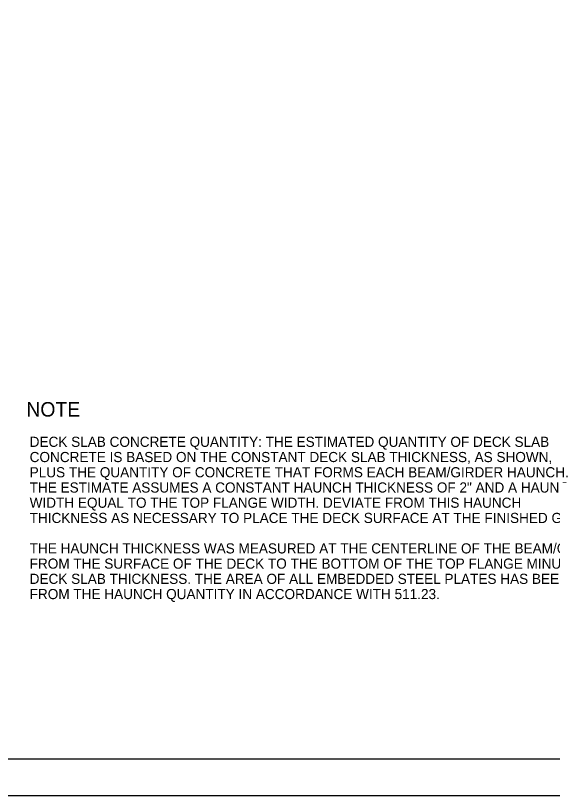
# Model space of a CAD drawing. Extents: x 0 to 34, y 0 to 22.
# Drawn here: x 22.86 to 30.27, y 0 to 10.76 of the extents above; entities that cross this region are included whole.
import ezdxf

# ---------------------------------------------------------------- set-up
doc = ezdxf.new("R2010")
doc.units = 0
for name, color, linetype in [('BR_P_Brg_Pad_Object', 7, 'Continuous'), ('BR_X_Brg_Centerline', 7, 'Continuous'), ('BR_X_Sub_Object', 7, 'Continuous')]:
    doc.layers.add(name, color=color, linetype=linetype)

msp = doc.modelspace()

# ---------------------------------------------------------------- linework, layer by layer
at = {"layer": 'BR_X_Brg_Centerline'}
msp.add_lwpolyline([(1.5, 21.5), (33.5, 21.5), (33.5, 0.5), (1.5, 0.5)], close=True, dxfattribs=at)
at = {"layer": 'BR_X_Sub_Object'}
msp.add_lwpolyline([(0, 0), (34, 0), (34, 22), (0, 22)], close=True, dxfattribs=at)

# ---------------------------------------------------------------- texts
at = {"layer": 'BR_P_Brg_Pad_Object'}
for s, height, p in [('NOTE', 0.2, (23.011, 5.225)), ('DECK SLAB CONCRETE QUANTITY: THE ESTIMATED QUANTITY OF DECK SLAB ', 0.14, (23.057, 4.807)), ('CONCRETE IS BASED ON THE CONSTANT DECK SLAB THICKNESS, AS SHOWN, ', 0.14, (23.057, 4.597)), ('PLUS THE QUANTITY OF CONCRETE THAT FORMS EACH BEAM/GIRDER HAUNCH. ', 0.14, (23.057, 4.387)), ('THE ESTIMATE ASSUMES A CONSTANT HAUNCH THICKNESS OF 2" AND A HAUNCH ', 0.14, (23.057, 4.177)), ('WIDTH EQUAL TO THE TOP FLANGE WIDTH. DEVIATE FROM THIS HAUNCH ', 0.14, (23.057, 3.967)), ('THICKNESS AS NECESSARY TO PLACE THE DECK SURFACE AT THE FINISHED GRADE.', 0.14, (23.057, 3.757)), ('THE HAUNCH THICKNESS WAS MEASURED AT THE CENTERLINE OF THE BEAM/GIRDER, ', 0.14, (23.057, 3.337)), ('FROM THE SURFACE OF THE DECK TO THE BOTTOM OF THE TOP FLANGE MINUS THE ', 0.14, (23.057, 3.127)), ('DECK SLAB THICKNESS. THE AREA OF ALL EMBEDDED STEEL PLATES HAS BEEN DEDUCTED ', 0.14, (23.057, 2.917)), ('FROM THE HAUNCH QUANTITY IN ACCORDANCE WITH 511.23.', 0.14, (23.057, 2.707))]:
    msp.add_text(s, height=height, dxfattribs=at).set_placement(p)

doc.saveas('drawing.dxf')
